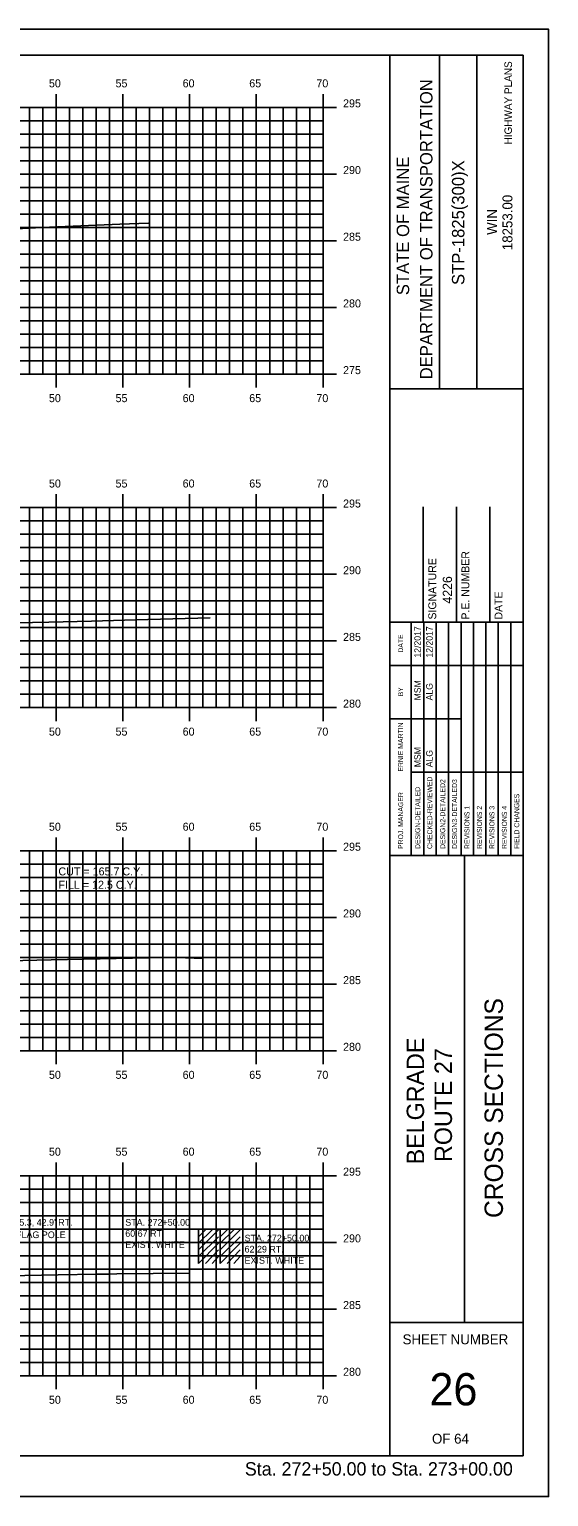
# Model space of a CAD drawing. Extents: x 852672 to 852842, y 366268 to 366378.
# Drawn here: x 852803.1 to 852842, y 366268.2 to 366378.2 of the extents above; entities that cross this region are included whole.
import ezdxf

# ---------------------------------------------------------------- set-up
doc = ezdxf.new("R2010")
doc.units = 0
for name, color, linetype in [('ANNOTATION', 7, 'Continuous'), ('BORDER', 7, 'Continuous'), ('D_Text_Monospaced', 7, 'Continuous'), ('H_V ANNOTATION', 7, 'Continuous'), ('HIGHWAY_TITLE', 7, 'Continuous'), ('MAJOR', 7, 'Continuous'), ('MINOR', 7, 'Continuous'), ('PLOT BOUNDARY', 7, 'Continuous'), ('S_Buildings', 7, 'Continuous'), ('S_Roadway_Centerline', 7, 'Continuous')]:
    doc.layers.add(name, color=color, linetype=linetype)

msp = doc.modelspace()

# ---------------------------------------------------------------- linework, layer by layer
at = {"layer": 'BORDER'}
for p, q in [((852840.1, 366376.24), (852680.1, 366376.24)), ((852830.1, 366271.24), (852830.1, 366376.24)), ((852833.83, 366351.23), (852833.83, 366376.23)), ((852836.62, 366351.23), (852836.62, 366376.23)), ((852840.1, 366271.24), (852840.1, 366376.24)), ((852830.1, 366351.23), (852840.1, 366351.23)), ((852832.6, 366333.74), (852832.6, 366342.39)), ((852835.1, 366333.74), (852835.1, 366342.39)), ((852837.6, 366333.74), (852837.6, 366342.39)), ((852830.1, 366333.74), (852840.1, 366333.74)), ((852830.1, 366316.24), (852840.1, 366316.24)), ((852835.69, 366281.24), (852835.69, 366316.24)), ((852830.1, 366281.24), (852840.1, 366281.24)), ((852680.1, 366271.24), (852840.1, 366271.24))]:
    msp.add_line(p, q, dxfattribs=at)
for points in [[(852831.71, 366330.49), (852831.71, 366333.74)], [(852831.71, 366316.24), (852831.71, 366333.03)], [(852832.64, 366316.24), (852832.64, 366333.74)], [(852833.58, 366333.74), (852833.58, 366316.24)], [(852834.51, 366316.24), (852834.51, 366333.74)], [(852835.44, 366316.24), (852835.44, 366333.74)], [(852836.37, 366316.24), (852836.37, 366333.74)], [(852837.3, 366316.24), (852837.3, 366333.74)], [(852838.23, 366316.24), (852838.23, 366333.74)], [(852839.17, 366316.24), (852839.17, 366333.74)], [(852830.1, 366330.49), (852840.1, 366330.49)], [(852830.1, 366326.49), (852831.71, 366326.49)], [(852831.71, 366326.49), (852835.44, 366326.49)], [(852831.71, 366322.49), (852840.1, 366322.49)]]:
    msp.add_lwpolyline(points, dxfattribs=at)
at = {"layer": 'MAJOR'}
for p, q in [((852805.1, 366373.33), (852805.1, 366372.33)), ((852810.1, 366373.33), (852810.1, 366372.33)), ((852815.1, 366373.33), (852815.1, 366372.33)), ((852820.1, 366373.33), (852820.1, 366372.33)), ((852825.1, 366373.33), (852825.1, 366372.33)), ((852685.1, 366372.33), (852825.1, 366372.33)), ((852685.1, 366372.33), (852825.1, 366372.33)), ((852805.1, 366352.33), (852805.1, 366372.33)), ((852810.1, 366352.33), (852810.1, 366372.33)), ((852815.1, 366352.33), (852815.1, 366372.33)), ((852820.1, 366352.33), (852820.1, 366372.33)), ((852826.1, 366372.33), (852824.09, 366372.33)), ((852825.1, 366352.33), (852825.1, 366372.33)), ((852825.1, 366352.33), (852825.1, 366372.33)), ((852685.1, 366367.33), (852825.1, 366367.33)), ((852826.1, 366367.33), (852824.09, 366367.33)), ((852685.1, 366362.33), (852825.1, 366362.33)), ((852826.1, 366362.33), (852824.09, 366362.33)), ((852685.1, 366357.33), (852825.1, 366357.33)), ((852826.1, 366357.33), (852824.09, 366357.33)), ((852685.1, 366352.33), (852825.1, 366352.33)), ((852685.1, 366352.33), (852825.1, 366352.33)), ((852805.1, 366351.32), (852805.1, 366352.33)), ((852810.1, 366351.32), (852810.1, 366352.33)), ((852815.1, 366351.32), (852815.1, 366352.33)), ((852820.1, 366351.32), (852820.1, 366352.33)), ((852826.1, 366352.33), (852824.09, 366352.33)), ((852825.1, 366351.32), (852825.1, 366352.33)), ((852805.1, 366343.33), (852805.1, 366342.33)), ((852810.1, 366343.33), (852810.1, 366342.33)), ((852815.1, 366343.33), (852815.1, 366342.33)), ((852820.1, 366343.33), (852820.1, 366342.33)), ((852825.1, 366343.33), (852825.1, 366342.33)), ((852685.1, 366342.33), (852825.1, 366342.33)), ((852685.1, 366342.33), (852825.1, 366342.33)), ((852805.1, 366327.33), (852805.1, 366342.33)), ((852810.1, 366327.33), (852810.1, 366342.33)), ((852815.1, 366327.33), (852815.1, 366342.33)), ((852820.1, 366327.33), (852820.1, 366342.33)), ((852826.1, 366342.33), (852824.09, 366342.33)), ((852825.1, 366327.33), (852825.1, 366342.33)), ((852825.1, 366327.33), (852825.1, 366342.33)), ((852685.1, 366337.33), (852825.1, 366337.33)), ((852826.1, 366337.33), (852824.09, 366337.33)), ((852685.1, 366332.33), (852825.1, 366332.33)), ((852826.1, 366332.33), (852824.09, 366332.33)), ((852685.1, 366327.33), (852825.1, 366327.33)), ((852685.1, 366327.33), (852825.1, 366327.33)), ((852805.1, 366326.32), (852805.1, 366327.33)), ((852810.1, 366326.32), (852810.1, 366327.33)), ((852815.1, 366326.32), (852815.1, 366327.33)), ((852820.1, 366326.32), (852820.1, 366327.33)), ((852826.1, 366327.33), (852824.09, 366327.33)), ((852825.1, 366326.32), (852825.1, 366327.33)), ((852805.1, 366317.6), (852805.1, 366316.6)), ((852810.1, 366317.6), (852810.1, 366316.6)), ((852815.1, 366317.6), (852815.1, 366316.6)), ((852820.1, 366317.6), (852820.1, 366316.6)), ((852825.1, 366317.6), (852825.1, 366316.6)), ((852685.1, 366316.6), (852825.1, 366316.6)), ((852685.1, 366316.6), (852825.1, 366316.6)), ((852805.1, 366301.6), (852805.1, 366316.6)), ((852810.1, 366301.6), (852810.1, 366316.6)), ((852815.1, 366301.6), (852815.1, 366316.6)), ((852820.1, 366301.6), (852820.1, 366316.6)), ((852826.1, 366316.6), (852824.09, 366316.6)), ((852825.1, 366301.6), (852825.1, 366316.6)), ((852825.1, 366301.6), (852825.1, 366316.6)), ((852685.1, 366311.6), (852825.1, 366311.6)), ((852826.1, 366311.6), (852824.09, 366311.6)), ((852685.1, 366306.6), (852825.1, 366306.6)), ((852826.1, 366306.6), (852824.09, 366306.6)), ((852685.1, 366301.6), (852825.1, 366301.6)), ((852685.1, 366301.6), (852825.1, 366301.6)), ((852805.1, 366300.6), (852805.1, 366301.6)), ((852810.1, 366300.6), (852810.1, 366301.6)), ((852815.1, 366300.6), (852815.1, 366301.6)), ((852820.1, 366300.6), (852820.1, 366301.6)), ((852826.1, 366301.6), (852824.09, 366301.6)), ((852825.1, 366300.6), (852825.1, 366301.6)), ((852805.1, 366293.24), (852805.1, 366292.24)), ((852810.1, 366293.24), (852810.1, 366292.24)), ((852815.1, 366293.24), (852815.1, 366292.24)), ((852820.1, 366293.24), (852820.1, 366292.24)), ((852825.1, 366293.24), (852825.1, 366292.24)), ((852685.1, 366292.24), (852825.1, 366292.24)), ((852685.1, 366292.24), (852825.1, 366292.24)), ((852805.1, 366277.24), (852805.1, 366292.24)), ((852810.1, 366277.24), (852810.1, 366292.24)), ((852815.1, 366277.24), (852815.1, 366292.24)), ((852820.1, 366277.24), (852820.1, 366292.24)), ((852826.1, 366292.24), (852824.09, 366292.24)), ((852825.1, 366277.24), (852825.1, 366292.24)), ((852825.1, 366277.24), (852825.1, 366292.24)), ((852685.1, 366287.24), (852825.1, 366287.24)), ((852826.1, 366287.24), (852824.09, 366287.24)), ((852685.1, 366282.24), (852825.1, 366282.24)), ((852826.1, 366282.24), (852824.09, 366282.24)), ((852685.1, 366277.24), (852825.1, 366277.24)), ((852805.1, 366276.23), (852805.1, 366277.24)), ((852810.1, 366276.23), (852810.1, 366277.24)), ((852815.1, 366276.23), (852815.1, 366277.24)), ((852820.1, 366276.23), (852820.1, 366277.24)), ((852826.1, 366277.24), (852824.09, 366277.24)), ((852825.1, 366276.23), (852825.1, 366277.24))]:
    msp.add_line(p, q, dxfattribs=at)
at = {"layer": 'MINOR'}
for p, q in [((852803.1, 366352.33), (852803.1, 366372.33)), ((852804.1, 366352.33), (852804.1, 366372.33)), ((852806.1, 366352.33), (852806.1, 366372.33)), ((852807.1, 366352.33), (852807.1, 366372.33)), ((852808.1, 366352.33), (852808.1, 366372.33)), ((852809.1, 366352.33), (852809.1, 366372.33)), ((852811.1, 366352.33), (852811.1, 366372.33)), ((852812.1, 366352.33), (852812.1, 366372.33)), ((852813.1, 366352.33), (852813.1, 366372.33)), ((852814.1, 366352.33), (852814.1, 366372.33)), ((852816.1, 366352.33), (852816.1, 366372.33)), ((852817.1, 366352.33), (852817.1, 366372.33)), ((852818.1, 366352.33), (852818.1, 366372.33)), ((852819.1, 366352.33), (852819.1, 366372.33)), ((852821.1, 366352.33), (852821.1, 366372.33)), ((852822.1, 366352.33), (852822.1, 366372.33)), ((852823.1, 366352.33), (852823.1, 366372.33)), ((852824.1, 366352.33), (852824.1, 366372.33)), ((852685.1, 366371.33), (852825.1, 366371.33)), ((852825.1, 366371.33), (852824.09, 366371.33)), ((852685.1, 366370.33), (852825.1, 366370.33)), ((852685.1, 366369.33), (852825.1, 366369.33)), ((852825.1, 366370.33), (852824.09, 366370.33)), ((852825.1, 366369.33), (852824.09, 366369.33)), ((852685.1, 366368.33), (852825.1, 366368.33)), ((852825.1, 366368.33), (852824.09, 366368.33)), ((852685.1, 366366.33), (852825.1, 366366.33)), ((852825.1, 366366.33), (852824.09, 366366.33)), ((852685.1, 366365.33), (852825.1, 366365.33)), ((852825.1, 366365.33), (852824.09, 366365.33)), ((852685.1, 366364.33), (852825.1, 366364.33)), ((852825.1, 366364.33), (852824.09, 366364.33)), ((852685.1, 366363.33), (852825.1, 366363.33)), ((852825.1, 366363.33), (852824.09, 366363.33)), ((852685.1, 366361.33), (852825.1, 366361.33)), ((852825.1, 366361.33), (852824.09, 366361.33)), ((852685.1, 366360.33), (852825.1, 366360.33)), ((852825.1, 366360.33), (852824.09, 366360.33)), ((852685.1, 366359.33), (852825.1, 366359.33)), ((852685.1, 366358.33), (852825.1, 366358.33)), ((852825.1, 366359.33), (852824.09, 366359.33)), ((852825.1, 366358.33), (852824.09, 366358.33)), ((852685.1, 366356.33), (852825.1, 366356.33)), ((852825.1, 366356.33), (852824.09, 366356.33)), ((852685.1, 366355.33), (852825.1, 366355.33)), ((852825.1, 366355.33), (852824.09, 366355.33)), ((852685.1, 366354.33), (852825.1, 366354.33)), ((852825.1, 366354.33), (852824.09, 366354.33)), ((852685.1, 366353.33), (852825.1, 366353.33)), ((852825.1, 366353.33), (852824.09, 366353.33)), ((852803.1, 366327.33), (852803.1, 366342.33)), ((852804.1, 366327.33), (852804.1, 366342.33)), ((852806.1, 366327.33), (852806.1, 366342.33)), ((852807.1, 366327.33), (852807.1, 366342.33)), ((852808.1, 366327.33), (852808.1, 366342.33)), ((852809.1, 366327.33), (852809.1, 366342.33)), ((852811.1, 366327.33), (852811.1, 366342.33)), ((852812.1, 366327.33), (852812.1, 366342.33)), ((852813.1, 366327.33), (852813.1, 366342.33)), ((852814.1, 366327.33), (852814.1, 366342.33)), ((852816.1, 366327.33), (852816.1, 366342.33)), ((852817.1, 366327.33), (852817.1, 366342.33)), ((852818.1, 366327.33), (852818.1, 366342.33)), ((852819.1, 366327.33), (852819.1, 366342.33)), ((852821.1, 366327.33), (852821.1, 366342.33)), ((852822.1, 366327.33), (852822.1, 366342.33)), ((852823.1, 366327.33), (852823.1, 366342.33)), ((852824.1, 366327.33), (852824.1, 366342.33)), ((852685.1, 366341.33), (852825.1, 366341.33)), ((852825.1, 366341.33), (852824.09, 366341.33)), ((852685.1, 366340.33), (852825.1, 366340.33)), ((852825.1, 366340.33), (852824.09, 366340.33)), ((852685.1, 366339.33), (852825.1, 366339.33)), ((852825.1, 366339.33), (852824.09, 366339.33)), ((852685.1, 366338.33), (852825.1, 366338.33)), ((852825.1, 366338.33), (852824.09, 366338.33)), ((852685.1, 366336.33), (852825.1, 366336.33)), ((852825.1, 366336.33), (852824.09, 366336.33)), ((852685.1, 366335.33), (852825.1, 366335.33)), ((852825.1, 366335.33), (852824.09, 366335.33)), ((852685.1, 366334.33), (852825.1, 366334.33)), ((852825.1, 366334.33), (852824.09, 366334.33)), ((852685.1, 366333.33), (852825.1, 366333.33)), ((852825.1, 366333.33), (852824.09, 366333.33)), ((852685.1, 366331.33), (852825.1, 366331.33)), ((852825.1, 366331.33), (852824.09, 366331.33)), ((852685.1, 366330.33), (852825.1, 366330.33)), ((852825.1, 366330.33), (852824.09, 366330.33)), ((852685.1, 366329.33), (852825.1, 366329.33)), ((852825.1, 366329.33), (852824.09, 366329.33)), ((852685.1, 366328.33), (852825.1, 366328.33)), ((852825.1, 366328.33), (852824.09, 366328.33)), ((852803.1, 366301.6), (852803.1, 366316.6)), ((852804.1, 366301.6), (852804.1, 366316.6)), ((852806.1, 366301.6), (852806.1, 366316.6)), ((852807.1, 366301.6), (852807.1, 366316.6)), ((852808.1, 366301.6), (852808.1, 366316.6)), ((852809.1, 366301.6), (852809.1, 366316.6)), ((852811.1, 366301.6), (852811.1, 366316.6)), ((852812.1, 366301.6), (852812.1, 366316.6)), ((852813.1, 366301.6), (852813.1, 366316.6)), ((852814.1, 366301.6), (852814.1, 366316.6)), ((852816.1, 366301.6), (852816.1, 366316.6)), ((852817.1, 366301.6), (852817.1, 366316.6)), ((852818.1, 366301.6), (852818.1, 366316.6)), ((852819.1, 366301.6), (852819.1, 366316.6)), ((852821.1, 366301.6), (852821.1, 366316.6)), ((852822.1, 366301.6), (852822.1, 366316.6)), ((852823.1, 366301.6), (852823.1, 366316.6)), ((852824.1, 366301.6), (852824.1, 366316.6)), ((852685.1, 366315.6), (852825.1, 366315.6)), ((852825.1, 366315.6), (852824.09, 366315.6)), ((852685.1, 366314.6), (852825.1, 366314.6)), ((852825.1, 366314.6), (852824.09, 366314.6)), ((852685.1, 366313.6), (852825.1, 366313.6)), ((852825.1, 366313.6), (852824.09, 366313.6)), ((852685.1, 366312.6), (852825.1, 366312.6)), ((852825.1, 366312.6), (852824.09, 366312.6)), ((852685.1, 366310.6), (852825.1, 366310.6)), ((852825.1, 366310.6), (852824.09, 366310.6)), ((852685.1, 366309.6), (852825.1, 366309.6)), ((852825.1, 366309.6), (852824.09, 366309.6)), ((852685.1, 366308.6), (852825.1, 366308.6)), ((852825.1, 366308.6), (852824.09, 366308.6)), ((852685.1, 366307.6), (852825.1, 366307.6)), ((852825.1, 366307.6), (852824.09, 366307.6)), ((852685.1, 366305.6), (852825.1, 366305.6)), ((852825.1, 366305.6), (852824.09, 366305.6)), ((852685.1, 366304.6), (852825.1, 366304.6)), ((852825.1, 366304.6), (852824.09, 366304.6)), ((852685.1, 366303.6), (852825.1, 366303.6)), ((852825.1, 366303.6), (852824.09, 366303.6)), ((852685.1, 366302.6), (852825.1, 366302.6)), ((852825.1, 366302.6), (852824.09, 366302.6)), ((852685.1, 366291.24), (852825.1, 366291.24)), ((852803.1, 366277.24), (852803.1, 366292.24)), ((852804.1, 366277.24), (852804.1, 366292.24)), ((852806.1, 366277.24), (852806.1, 366292.24)), ((852807.1, 366277.24), (852807.1, 366292.24)), ((852808.1, 366277.24), (852808.1, 366292.24)), ((852809.1, 366277.24), (852809.1, 366292.24)), ((852811.1, 366277.24), (852811.1, 366292.24)), ((852812.1, 366277.24), (852812.1, 366292.24)), ((852813.1, 366277.24), (852813.1, 366292.24)), ((852814.1, 366277.24), (852814.1, 366292.24)), ((852816.1, 366277.24), (852816.1, 366292.24)), ((852817.1, 366277.24), (852817.1, 366292.24)), ((852818.1, 366277.24), (852818.1, 366292.24)), ((852819.1, 366277.24), (852819.1, 366292.24)), ((852821.1, 366277.24), (852821.1, 366292.24)), ((852822.1, 366277.24), (852822.1, 366292.24)), ((852823.1, 366277.24), (852823.1, 366292.24)), ((852825.1, 366291.24), (852824.09, 366291.24)), ((852824.1, 366277.24), (852824.1, 366292.24)), ((852685.1, 366290.24), (852825.1, 366290.24)), ((852825.1, 366290.24), (852824.09, 366290.24)), ((852685.1, 366289.24), (852825.1, 366289.24)), ((852825.1, 366289.24), (852824.09, 366289.24)), ((852685.1, 366288.24), (852825.1, 366288.24)), ((852825.1, 366288.24), (852824.09, 366288.24)), ((852685.1, 366286.24), (852825.1, 366286.24)), ((852825.1, 366286.24), (852824.09, 366286.24)), ((852685.1, 366285.24), (852825.1, 366285.24)), ((852825.1, 366285.24), (852824.09, 366285.24)), ((852685.1, 366284.24), (852825.1, 366284.24)), ((852825.1, 366284.24), (852824.09, 366284.24)), ((852685.1, 366283.24), (852825.1, 366283.24)), ((852825.1, 366283.24), (852824.09, 366283.24)), ((852685.1, 366281.24), (852825.1, 366281.24)), ((852685.1, 366280.24), (852825.1, 366280.24)), ((852825.1, 366281.24), (852824.09, 366281.24)), ((852825.1, 366280.24), (852824.09, 366280.24)), ((852685.1, 366279.24), (852825.1, 366279.24)), ((852825.1, 366279.24), (852824.09, 366279.24)), ((852685.1, 366278.24), (852825.1, 366278.24)), ((852825.1, 366278.24), (852824.09, 366278.24))]:
    msp.add_line(p, q, dxfattribs=at)
at = {"layer": 'PLOT BOUNDARY'}
msp.add_lwpolyline([(852672, 366268.18), (852842, 366268.18), (852842, 366378.18), (852672, 366378.18)], close=True, dxfattribs=at)
at = {"layer": 'S_Buildings'}
for p, q in [((852815.76, 366285.66), (852815.76, 366288.19)), ((852815.76, 366286.68), (852817.27, 366288.19)), ((852815.76, 366287.17), (852816.78, 366288.19)), ((852815.76, 366287.66), (852816.29, 366288.19)), ((852817.39, 366285.66), (852817.39, 366288.19)), ((852817.39, 366286.68), (852818.9, 366288.19)), ((852817.39, 366287.17), (852818.41, 366288.19)), ((852817.39, 366287.66), (852817.91, 366288.19)), ((852815.76, 366286.19), (852817.27, 366287.66)), ((852815.76, 366285.66), (852817.27, 366287.17)), ((852817.39, 366286.19), (852818.9, 366287.66)), ((852817.39, 366285.66), (852818.9, 366287.17)), ((852816.29, 366285.66), (852817.27, 366286.68)), ((852816.78, 366285.66), (852817.27, 366286.19)), ((852817.91, 366285.66), (852818.9, 366286.68)), ((852818.41, 366285.66), (852818.9, 366286.19))]:
    msp.add_line(p, q, dxfattribs=at)
at = {"layer": 'S_Roadway_Centerline'}
for points in [[(852706.61, 366362), (852711.43, 366361.99), (852721.19, 366361.85), (852723.22, 366361.85), (852731.3, 366362.17), (852732, 366362.15), (852734.14, 366361.93), (852735.02, 366362.06), (852736.93, 366362.33), (852740.77, 366362.63), (852743.13, 366362.79), (852747.42, 366362.87), (852755.19, 366363.08), (852759.99, 366362.96), (852768.42, 366362.72), (852776.31, 366362.41), (852781.43, 366362.26), (852782.59, 366362.29), (852784.41, 366362.38), (852787.29, 366362.4), (852792.84, 366362.75), (852804.04, 366363.31), (852809.88, 366363.56), (852812.01, 366363.65)], [(852792.26, 366333.49), (852804.55, 366333.74), (852807.75, 366333.8), (852811.05, 366333.9), (852816.64, 366334.06)], [(852728.87, 366307.44), (852729.91, 366307.44), (852730.78, 366307.48), (852730.86, 366307.47), (852734.11, 366307.13), (852734.2, 366307.15), (852737.09, 366307.56), (852742.93, 366308.02), (852743.15, 366308.03), (852743.53, 366308.04), (852755.3, 366308.36), (852755.84, 366308.34), (852768.63, 366307.98), (852769.51, 366307.94), (852770.53, 366307.91), (852776.81, 366307.75), (852781.25, 366307.62), (852788.24, 366307.88), (852797.25, 366308.25), (852804.72, 366308.43), (852813.27, 366308.59), (852814.8, 366308.57), (852816.08, 366308.53)], [(852796.45, 366284.63), (852805.26, 366284.8), (852808.13, 366284.85), (852809.16, 366284.86), (852809.65, 366284.88), (852815.09, 366284.92)]]:
    msp.add_lwpolyline(points, dxfattribs=at)

# ---------------------------------------------------------------- texts
at = {"layer": 'ANNOTATION'}
msp.add_text('4226', height=0.69, rotation=90, dxfattribs=at).set_placement((852834.76, 366335.13))
for s, p in [('CUT = 165.7 C.Y.', (852805.27, 366314.75)), ('FILL = 12.5 C.Y.', (852805.27, 366313.75))]:
    msp.add_text(s, height=0.6, dxfattribs=at).set_placement(p)
at = {"layer": 'BORDER'}
for s, height, rotation, p in [('DEPARTMENT OF TRANSPORTATION', 0.9318, 90, (852833.3, 366351.94)), ('STATE OF MAINE', 0.9318, 90, (852831.55, 366358.25)), ('STP-1825(300)X', 0.9318, 90, (852835.69, 366359.01)), ('18253.00', 0.745, 90, (852839.29, 366361.62)), ('WIN', 0.745, 90, (852838.13, 366362.77)), ('SIGNATURE', 0.591, 90, (852833.58, 366333.93)), ('P.E. NUMBER', 0.5906, 90, (852836.06, 366333.93)), ('DATE', 0.591, 90, (852838.54, 366333.93)), ('12/2017', 0.485, 90, (852832.42, 366331.08)), ('12/2017', 0.485, 90, (852833.31, 366331.08)), ('DATE', 0.371, 90, (852831.1, 366331.45)), ('BY', 0.371, 90, (852831.1, 366328.17)), ('MSM', 0.485, 90, (852832.42, 366327.87)), ('ALG', 0.485, 90, (852833.31, 366327.87)), ('ERNIE MARTIN', 0.3727, 90, (852831.1, 366322.53)), ('MSM', 0.485, 90, (852832.42, 366322.86)), ('ALG', 0.485, 90, (852833.31, 366322.86)), ('DESIGN-DETAILED', 0.3727, 90, (852832.38, 366316.73)), ('CHECKED-REVIEWED', 0.3727, 90, (852833.28, 366316.73)), ('DESIGN2-DETAILED2', 0.3727, 90, (852834.25, 366316.73)), ('DESIGN3-DETAILED3', 0.3727, 90, (852835.14, 366316.73)), ('PROJ. MANAGER', 0.3727, 90, (852831.1, 366316.73)), ('REVISIONS 1', 0.3727, 90, (852836.07, 366316.73)), ('REVISIONS 2', 0.3727, 90, (852837, 366316.73)), ('REVISIONS 3', 0.3727, 90, (852837.94, 366316.73)), ('REVISIONS 4', 0.3727, 90, (852838.87, 366316.73)), ('FIELD CHANGES', 0.3727, 90, (852839.8, 366316.73)), ('CROSS SECTIONS', 1.3779, 90, (852838.58, 366289.07)), ('SHEET NUMBER', 0.7453, 360, (852831.06, 366279.6)), ('26', 2.419, 360, (852833.07, 366275.02)), ('OF 64', 0.745, 360, (852833.26, 366272.15))]:
    msp.add_text(s, height=height, rotation=rotation, dxfattribs=at).set_placement(p)
at = {"layer": 'D_Text_Monospaced'}
for s, p in [("STA. 272+55.3, 42.9' RT.", (852798.79, 366288.49)), ('EXISTING FLAG POLE', (852798.79, 366287.56)), ('STA. 272+50.00', (852810.28, 366288.49)), ('60.67 RT.', (852810.28, 366287.66)), ('EXIST. WHITE', (852810.28, 366286.82)), ('STA. 272+50.00', (852819.22, 366287.31)), ('62.29 RT.', (852819.22, 366286.48)), ('EXIST. WHITE', (852819.22, 366285.64))]:
    msp.add_text(s, height=0.5, dxfattribs=at).set_placement(p)
at = {"layer": 'H_V ANNOTATION'}
for s, height, p in [('50', 0.6, (852804.56, 366373.83)), ('55', 0.6, (852809.55, 366373.83)), ('60', 0.6, (852814.58, 366373.83)), ('65', 0.6, (852819.57, 366373.83)), ('70', 0.6, (852824.6, 366373.83)), ('295', 0.6, (852826.6, 366372.33)), ('290', 0.6, (852826.6, 366367.33)), ('285', 0.6, (852826.6, 366362.33)), ('280', 0.6, (852826.6, 366357.33)), ('275', 0.6, (852826.6, 366352.33)), ('50', 0.6, (852804.56, 366350.23)), ('55', 0.6, (852809.55, 366350.23)), ('60', 0.6, (852814.58, 366350.23)), ('65', 0.6, (852819.57, 366350.23)), ('70', 0.6, (852824.6, 366350.23)), ('50', 0.6, (852804.56, 366343.83)), ('55', 0.6, (852809.55, 366343.83)), ('60', 0.6, (852814.58, 366343.83)), ('65', 0.6, (852819.57, 366343.83)), ('70', 0.6, (852824.6, 366343.83)), ('295', 0.6, (852826.6, 366342.33)), ('290', 0.6, (852826.6, 366337.33)), ('285', 0.6, (852826.6, 366332.33)), ('280', 0.6, (852826.6, 366327.33)), ('50', 0.6, (852804.56, 366325.23)), ('55', 0.6, (852809.55, 366325.23)), ('60', 0.6, (852814.58, 366325.23)), ('65', 0.6, (852819.57, 366325.23)), ('70', 0.6, (852824.6, 366325.23)), ('50', 0.6, (852804.56, 366318.1)), ('55', 0.6, (852809.55, 366318.1)), ('60', 0.6, (852814.58, 366318.1)), ('65', 0.6, (852819.57, 366318.1)), ('70', 0.6, (852824.6, 366318.1)), ('295', 0.6, (852826.6, 366316.6)), ('290', 0.6, (852826.6, 366311.6)), ('285', 0.6, (852826.6, 366306.6)), ('280', 0.6, (852826.6, 366301.6)), ('50', 0.6, (852804.56, 366299.5)), ('55', 0.6, (852809.55, 366299.5)), ('60', 0.6, (852814.58, 366299.5)), ('65', 0.6, (852819.57, 366299.5)), ('70', 0.6, (852824.6, 366299.5)), ('50', 0.6, (852804.56, 366293.74)), ('55', 0.6, (852809.55, 366293.74)), ('60', 0.6, (852814.58, 366293.74)), ('65', 0.6, (852819.57, 366293.74)), ('70', 0.6, (852824.6, 366293.74)), ('295', 0.6, (852826.6, 366292.24)), ('290', 0.6, (852826.6, 366287.24)), ('285', 0.6, (852826.6, 366282.24)), ('280', 0.6, (852826.6, 366277.24)), ('50', 0.6, (852804.56, 366275.14)), ('55', 0.6, (852809.55, 366275.14)), ('60', 0.6, (852814.58, 366275.14)), ('65', 0.6, (852819.57, 366275.14)), ('70', 0.6, (852824.6, 366275.14)), ('Sta. 272+50.00 to Sta. 273+00.00', 1.0002, (852819.24, 366269.76))]:
    msp.add_text(s, height=height, dxfattribs=at).set_placement(p)
at = {"layer": 'HIGHWAY_TITLE'}
for s, height, p in [('HIGHWAY PLANS', 0.559, (852839.25, 366369.55)), ('BELGRADE', 1.304, (852832.67, 366293.09)), ('ROUTE 27', 1.304, (852834.76, 366293.27))]:
    msp.add_text(s, height=height, rotation=90, dxfattribs=at).set_placement(p)

doc.saveas('drawing.dxf')
